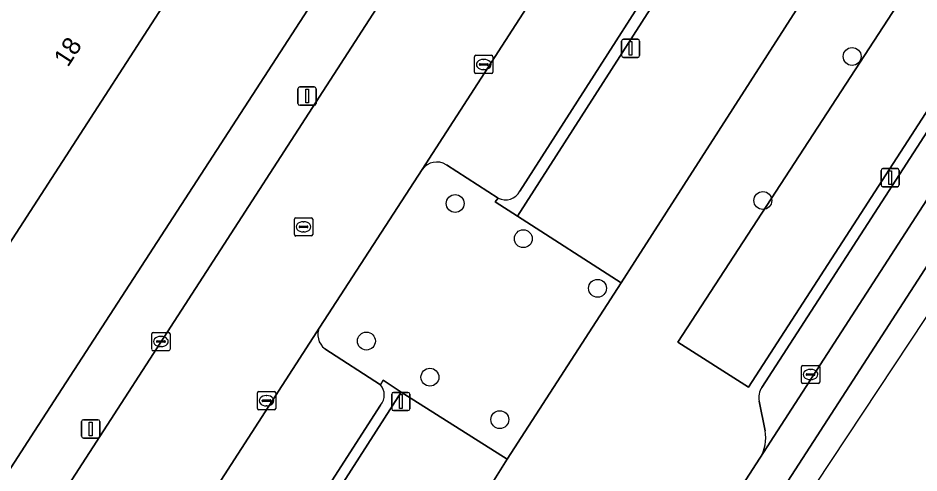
# Model space of a CAD drawing. Extents: x 161139 to 161601, y 381708 to 382245.
# Drawn here: x 161469.39 to 161518.67, y 381997.72 to 382022.6 of the extents above; entities that cross this region are included whole.
import ezdxf

# ---------------------------------------------------------------- set-up
doc = ezdxf.new("R2010")
doc.units = 0
for name, color, linetype in [('IMGEO_Boom', 7, 'Continuous'), ('IMGEO_Erf', 7, 'Continuous'), ('IMGEO_Groenvoorziening', 7, 'Continuous'), ('IMGEO_Kolk', 7, 'Continuous'), ('IMGEO_Lichtmast', 7, 'Continuous'), ('IMGEO_Pand', 7, 'Continuous'), ('IMGEO_Pand_nummerreeks', 7, 'Continuous'), ('IMGEO_Parkeervlak_open', 7, 'Continuous'), ('IMGEO_Rijbaan_lokaal_gesloten', 7, 'Continuous'), ('IMGEO_Rijbaan_lokaal_open', 7, 'Continuous'), ('IMGEO_Rioolput', 7, 'Continuous'), ('IMGEO_Voetpad_open', 7, 'Continuous')]:
    doc.layers.add(name, color=color, linetype=linetype)

msp = doc.modelspace()

# ---------------------------------------------------------------- linework, layer by layer
at = {"layer": 'IMGEO_Boom'}
for centre in [(161515.014, 382020.495), (161493.303, 382012.455), (161510.134, 382012.617), (161497.03, 382010.529), (161501.091, 382007.818), (161488.447, 382004.932), (161491.921, 382002.955), (161495.742, 382000.635)]:
    msp.add_circle(centre, 0.489, dxfattribs=at)
at = {"layer": 'IMGEO_Erf'}
msp.add_lwpolyline([(161320.525, 382089.631), (161313.623, 382083.997), (161443.483, 382000), (161462.38, 381987.777), (161470.3, 382000), (161498.24, 382043.117), (161359.011, 382133.266)], dxfattribs=at)
msp.add_lwpolyline([(161465.14, 382043.824), (161467.861, 382048.029), (161476.169, 382042.655), (161476.375, 382042.973), (161486.031, 382036.726), (161463.237, 382001.496), (161453.51, 382007.789), (161458.187, 382015.018), (161459.285, 382014.308), (161462.86, 382019.835), (161460.857, 382021.131), (161461.57, 382022.233), (161460.898, 382022.668), (161459.22, 382020.074), (161456.379, 382021.912), (161458.057, 382024.506), (161451.086, 382029.016), (161453.802, 382033.215), (161455.991, 382036.598), (161466.421, 382029.851), (161466.963, 382030.689), (161462.496, 382033.579), (161463.339, 382034.883), (161460.531, 382036.7)], close=True, dxfattribs=at)
at = {"layer": 'IMGEO_Groenvoorziening'}
for points in [[(161508.122, 382030.748), (161508.66, 382030.403), (161496.714, 382011.755), (161502.377, 382008.114), (161503.136, 382009.288), (161516.685, 382030.422)], [(161521.27, 382028.087), (161520.791, 382028.402), (161505.482, 382004.864), (161509.353, 382002.408), (161522.399, 382022.591)], [(161495.145, 381996.879), (161496.146, 381998.479), (161490.355, 382002.133), (161478.633, 381983.86), (161478.108, 381984.171)]]:
    msp.add_lwpolyline(points, dxfattribs=at)
at = {"layer": 'IMGEO_Kolk'}
for p, q in [((161494.363, 382019.63), (161494.363, 382020.482)), ((161494.438, 382020.556), (161495.29, 382020.556)), ((161494.851, 382020.336), (161494.876, 382020.336)), ((161495.364, 382020.482), (161495.364, 382019.63)), ((161494.622, 382020.05), (161494.622, 382020.062)), ((161495.06, 382020.013), (161494.662, 382020.013)), ((161494.665, 382020.099), (161495.063, 382020.099)), ((161494.874, 382019.776), (161494.849, 382019.776)), ((161495.106, 382020.062), (161495.106, 382020.05)), ((161495.29, 382019.556), (161494.438, 382019.556)), ((161476.707, 382004.48), (161476.707, 382005.332)), ((161476.782, 382005.406), (161477.634, 382005.406)), ((161477.195, 382005.186), (161477.22, 382005.186)), ((161477.708, 382005.332), (161477.708, 382004.48)), ((161476.966, 382004.9), (161476.966, 382004.912)), ((161477.404, 382004.863), (161477.006, 382004.863)), ((161477.009, 382004.949), (161477.407, 382004.949)), ((161477.218, 382004.626), (161477.193, 382004.626)), ((161477.45, 382004.912), (161477.45, 382004.9)), ((161477.634, 382004.406), (161476.782, 382004.406)), ((161512.241, 382002.678), (161512.241, 382003.53)), ((161512.316, 382003.604), (161513.168, 382003.604)), ((161513.242, 382003.53), (161513.242, 382002.678)), ((161512.5, 382003.098), (161512.5, 382003.11)), ((161512.938, 382003.061), (161512.54, 382003.061)), ((161512.543, 382003.147), (161512.941, 382003.147)), ((161512.729, 382003.384), (161512.754, 382003.384)), ((161512.984, 382003.11), (161512.984, 382003.098)), ((161513.168, 382002.604), (161512.316, 382002.604)), ((161512.752, 382002.824), (161512.727, 382002.824)), ((161482.484, 382001.243), (161482.484, 382002.095)), ((161482.559, 382002.169), (161483.411, 382002.169)), ((161483.485, 382002.095), (161483.485, 382001.243)), ((161482.743, 382001.663), (161482.743, 382001.675)), ((161483.181, 382001.626), (161482.783, 382001.626)), ((161482.786, 382001.712), (161483.184, 382001.712)), ((161482.972, 382001.949), (161482.997, 382001.949)), ((161483.227, 382001.675), (161483.227, 382001.663)), ((161483.411, 382001.169), (161482.559, 382001.169)), ((161482.995, 382001.389), (161482.97, 382001.389))]:
    msp.add_line(p, q, dxfattribs=at)
for points in [[(161494.363, 382019.63), (161494.363, 382020.482)], [(161494.438, 382020.556), (161495.29, 382020.556)], [(161495.364, 382020.482), (161495.364, 382019.63)], [(161495.29, 382019.556), (161494.438, 382019.556)], [(161476.707, 382004.48), (161476.707, 382005.332)], [(161476.782, 382005.406), (161477.634, 382005.406)], [(161477.708, 382005.332), (161477.708, 382004.48)], [(161477.634, 382004.406), (161476.782, 382004.406)], [(161512.241, 382002.678), (161512.241, 382003.53)], [(161512.316, 382003.604), (161513.168, 382003.604)], [(161513.242, 382003.53), (161513.242, 382002.678)], [(161513.168, 382002.604), (161512.316, 382002.604)], [(161482.484, 382001.243), (161482.484, 382002.095)], [(161482.559, 382002.169), (161483.411, 382002.169)], [(161483.485, 382002.095), (161483.485, 382001.243)], [(161483.411, 382001.169), (161482.559, 382001.169)]]:
    msp.add_lwpolyline(points, dxfattribs=at)
for centre, radius, start, end in [((161494.44, 382020.48), 0.0765, 91.552, 178.448), ((161494.44, 382020.48), 0.0765, 91.552, 178.448), ((161495.288, 382020.48), 0.0765, 1.552, 88.448), ((161495.288, 382020.48), 0.0765, 1.552, 88.448), ((161494.662, 382020.059), 0.0403, 85.8775, 175.7526), ((161494.659, 382020.049), 0.0366, 178.938, 274.7102), ((161495.063, 382020.056), 0.043, 264.8664, 352.4533), ((161495.067, 382020.061), 0.0386, 1.7309, 96.639), ((161494.44, 382019.632), 0.0765, 181.552, 268.448), ((161494.44, 382019.632), 0.0765, 181.552, 268.448), ((161495.288, 382019.632), 0.0765, 271.552, 358.448), ((161495.288, 382019.632), 0.0765, 271.552, 358.448), ((161476.784, 382005.33), 0.0765, 91.552, 178.448), ((161476.784, 382005.33), 0.0765, 91.552, 178.448), ((161477.632, 382005.33), 0.0765, 1.552, 88.448), ((161477.632, 382005.33), 0.0765, 1.552, 88.448), ((161477.006, 382004.909), 0.0403, 85.8775, 175.7526), ((161477.003, 382004.899), 0.0366, 178.938, 274.7102), ((161477.407, 382004.906), 0.043, 264.8664, 352.4533), ((161477.411, 382004.911), 0.0386, 1.7309, 96.639), ((161476.784, 382004.482), 0.0765, 181.552, 268.448), ((161476.784, 382004.482), 0.0765, 181.552, 268.448), ((161477.632, 382004.482), 0.0765, 271.552, 358.448), ((161477.632, 382004.482), 0.0765, 271.552, 358.448), ((161512.318, 382003.528), 0.0765, 91.552, 178.448), ((161512.318, 382003.528), 0.0765, 91.552, 178.448), ((161513.166, 382003.528), 0.0765, 1.552, 88.448), ((161513.166, 382003.528), 0.0765, 1.552, 88.448), ((161512.54, 382003.107), 0.0403, 85.8775, 175.7526), ((161512.537, 382003.097), 0.0366, 178.938, 274.7102), ((161512.941, 382003.104), 0.043, 264.8664, 352.4533), ((161512.945, 382003.109), 0.0386, 1.7309, 96.639), ((161512.318, 382002.68), 0.0765, 181.552, 268.448), ((161512.318, 382002.68), 0.0765, 181.552, 268.448), ((161513.166, 382002.68), 0.0765, 271.552, 358.448), ((161513.166, 382002.68), 0.0765, 271.552, 358.448), ((161482.561, 382002.093), 0.0765, 91.552, 178.448), ((161482.561, 382002.093), 0.0765, 91.552, 178.448), ((161483.409, 382002.093), 0.0765, 1.552, 88.448), ((161483.409, 382002.093), 0.0765, 1.552, 88.448), ((161482.783, 382001.672), 0.0403, 85.8775, 175.7526), ((161482.78, 382001.662), 0.0366, 178.938, 274.7102), ((161483.184, 382001.669), 0.043, 264.8664, 352.4533), ((161483.188, 382001.674), 0.0386, 1.7309, 96.639), ((161482.561, 382001.245), 0.0765, 181.552, 268.448), ((161482.561, 382001.245), 0.0765, 181.552, 268.448), ((161483.409, 382001.245), 0.0765, 271.552, 358.448), ((161483.409, 382001.245), 0.0765, 271.552, 358.448)]:
    msp.add_arc(centre, radius, start, end, dxfattribs=at)
for centre, major_axis, ratio, start_param, end_param in [((161494.85, 382020.056), (-0.387, 0.002), 0.722429, 4.712389, 7.853982), ((161494.875, 382020.056), (-0.39, 0.002), 0.717154, 1.570796, 4.712389), ((161477.194, 382004.906), (-0.387, 0.002), 0.722429, 4.712389, 7.853982), ((161477.219, 382004.906), (-0.39, 0.002), 0.717154, 1.570796, 4.712389), ((161512.728, 382003.104), (-0.387, 0.002), 0.722429, 4.712389, 7.853982), ((161512.753, 382003.104), (-0.39, 0.002), 0.717154, 1.570796, 4.712389), ((161482.971, 382001.669), (-0.387, 0.002), 0.722429, 4.712389, 7.853982), ((161482.996, 382001.669), (-0.39, 0.002), 0.717154, 1.570796, 4.712389)]:
    msp.add_ellipse(centre, major_axis=major_axis, ratio=ratio, start_param=start_param, end_param=end_param, dxfattribs=at)
at = {"layer": 'IMGEO_Lichtmast'}
for p, q in [((161502.403, 382020.538), (161502.403, 382021.338)), ((161502.403, 382021.338), (161502.403, 382020.538)), ((161502.503, 382021.438), (161503.293, 382021.438)), ((161503.293, 382021.438), (161502.503, 382021.438)), ((161503.393, 382021.338), (161503.393, 382020.538)), ((161503.393, 382020.538), (161503.393, 382021.338)), ((161503.293, 382020.438), (161502.503, 382020.438)), ((161502.503, 382020.438), (161503.293, 382020.438)), ((161484.805, 382018.828), (161485.595, 382018.828)), ((161485.595, 382018.828), (161484.805, 382018.828)), ((161484.705, 382017.928), (161484.705, 382018.728)), ((161484.705, 382018.728), (161484.705, 382017.928)), ((161485.695, 382018.728), (161485.695, 382017.928)), ((161485.695, 382017.928), (161485.695, 382018.728)), ((161485.595, 382017.828), (161484.805, 382017.828)), ((161484.805, 382017.828), (161485.595, 382017.828)), ((161516.699, 382014.366), (161517.489, 382014.366)), ((161517.489, 382014.366), (161516.699, 382014.366)), ((161516.599, 382013.466), (161516.599, 382014.266)), ((161516.599, 382014.266), (161516.599, 382013.466)), ((161517.589, 382014.266), (161517.589, 382013.466)), ((161517.589, 382013.466), (161517.589, 382014.266)), ((161517.489, 382013.366), (161516.699, 382013.366)), ((161516.699, 382013.366), (161517.489, 382013.366)), ((161489.831, 382001.227), (161489.831, 382002.027)), ((161489.831, 382002.027), (161489.831, 382001.227)), ((161489.931, 382002.127), (161490.721, 382002.127)), ((161490.721, 382002.127), (161489.931, 382002.127)), ((161490.821, 382002.027), (161490.821, 382001.227)), ((161490.821, 382001.227), (161490.821, 382002.027)), ((161490.721, 382001.127), (161489.931, 382001.127)), ((161489.931, 382001.127), (161490.721, 382001.127)), ((161472.971, 382000.629), (161473.761, 382000.629)), ((161473.761, 382000.629), (161472.971, 382000.629)), ((161472.871, 381999.729), (161472.871, 382000.529)), ((161472.871, 382000.529), (161472.871, 381999.729)), ((161473.861, 382000.529), (161473.861, 381999.729)), ((161473.861, 381999.729), (161473.861, 382000.529)), ((161473.761, 381999.629), (161472.971, 381999.629)), ((161472.971, 381999.629), (161473.761, 381999.629))]:
    msp.add_line(p, q, dxfattribs=at)
for points in [[(161502.823, 382021.313), (161502.973, 382021.313), (161502.973, 382020.563), (161502.823, 382020.563), (161502.823, 382021.313)], [(161485.125, 382018.703), (161485.275, 382018.703), (161485.275, 382017.953), (161485.125, 382017.953), (161485.125, 382018.703)], [(161517.019, 382014.241), (161517.169, 382014.241), (161517.169, 382013.491), (161517.019, 382013.491), (161517.019, 382014.241)], [(161490.251, 382002.002), (161490.401, 382002.002), (161490.401, 382001.252), (161490.251, 382001.252), (161490.251, 382002.002)], [(161473.291, 382000.504), (161473.441, 382000.504), (161473.441, 381999.754), (161473.291, 381999.754), (161473.291, 382000.504)]]:
    msp.add_lwpolyline(points, dxfattribs=at)
for centre, start, end in [((161502.503, 382021.338), 90, 180), ((161502.503, 382021.338), 90, 180), ((161503.293, 382021.338), 0, 90), ((161503.293, 382021.338), 360, 90), ((161502.503, 382020.538), 180, 270), ((161502.503, 382020.538), 180, 270), ((161503.293, 382020.538), 270, 0), ((161503.293, 382020.538), 270, 0), ((161484.805, 382018.728), 90, 180), ((161484.805, 382018.728), 90, 180), ((161485.595, 382018.728), 0, 90), ((161485.595, 382018.728), 360, 90), ((161484.805, 382017.928), 180, 270), ((161484.805, 382017.928), 180, 270), ((161485.595, 382017.928), 270, 0), ((161485.595, 382017.928), 270, 0), ((161516.699, 382014.266), 90, 180), ((161516.699, 382014.266), 90, 180), ((161517.489, 382014.266), 0, 90), ((161517.489, 382014.266), 360, 90), ((161516.699, 382013.466), 180, 270), ((161516.699, 382013.466), 180, 270), ((161517.489, 382013.466), 270, 0), ((161517.489, 382013.466), 270, 0), ((161489.931, 382002.027), 90, 180), ((161489.931, 382002.027), 90, 180), ((161490.721, 382002.027), 0, 90), ((161490.721, 382002.027), 360, 90), ((161489.931, 382001.227), 180, 270), ((161489.931, 382001.227), 180, 270), ((161490.721, 382001.227), 270, 0), ((161490.721, 382001.227), 270, 0), ((161472.971, 382000.529), 90, 180), ((161472.971, 382000.529), 90, 180), ((161473.761, 382000.529), 0, 90), ((161473.761, 382000.529), 360, 90), ((161472.971, 381999.729), 180, 270), ((161472.971, 381999.729), 180, 270), ((161473.761, 381999.729), 270, 0), ((161473.761, 381999.729), 270, 0)]:
    msp.add_arc(centre, 0.1, start, end, dxfattribs=at)
at = {"layer": 'IMGEO_Pand'}
msp.add_lwpolyline([(161486.031, 382036.726), (161476.375, 382042.973), (161476.169, 382042.655), (161467.861, 382048.029), (161465.14, 382043.824), (161460.531, 382036.7), (161463.339, 382034.883), (161462.496, 382033.579), (161466.963, 382030.689), (161466.421, 382029.851), (161455.991, 382036.598), (161453.802, 382033.215), (161451.086, 382029.016), (161458.057, 382024.506), (161456.379, 382021.912), (161459.22, 382020.074), (161460.898, 382022.668), (161461.57, 382022.233), (161460.857, 382021.131), (161462.86, 382019.835), (161459.285, 382014.308), (161458.187, 382015.018), (161453.51, 382007.789), (161463.237, 382001.496)], close=True, dxfattribs=at)
at = {"layer": 'IMGEO_Parkeervlak_open'}
for points in [[(161504.966, 382035.175), (161491.489, 382014.315)], [(161496.841, 382013.134), (161508.122, 382030.748)], [(161509.971, 381998.522), (161525.295, 382022.249)], [(161522.031, 382020.897), (161510.074, 382002.396)], [(161492.819, 382014.575), (161495.645, 382012.744)], [(161485.898, 382005.698), (161472.847, 381985.485), (161473.39, 381985.794)], [(161489.222, 382002.546), (161486.182, 382004.514)], [(161509.927, 382001.645), (161510.252, 382000.03)], [(161478.108, 381984.171), (161489.225, 382001.433)]]:
    msp.add_lwpolyline(points, dxfattribs=at)
for centre, radius, start, end in [((161492.296, 382013.717), 1.005, 58.664, 143.4584), ((161496.039, 382013.564), 0.91, 244.3382, 331.7827), ((161486.719, 382005.269), 0.926, 152.3859, 234.5909), ((161488.547, 382001.988), 0.876, 320.7099, 39.599), ((161510.848, 382001.855), 0.944, 145.0204, 192.8296), ((161508.23, 381999.627), 2.062, 327.6032, 11.2859)]:
    msp.add_arc(centre, radius, start, end, dxfattribs=at)
at = {"layer": 'IMGEO_Rijbaan_lokaal_gesloten'}
msp.add_lwpolyline([(161494.211, 381970.546), (161527.059, 382021.311), (161525.43, 382022.403), (161525.295, 382022.249), (161509.971, 381998.522), (161507.874, 381995.285), (161492.716, 381971.881), (161492.536, 381971.604)], close=True, dxfattribs=at)
at = {"layer": 'IMGEO_Rijbaan_lokaal_open'}
for points in [[(161500.799, 382041.385), (161464.955, 381985.959)], [(161485.898, 382005.698), (161491.489, 382014.315), (161504.966, 382035.175), (161506.503, 382037.599), (161506.547, 382037.659), (161506.592, 382037.718)], [(161470.158, 381981.373), (161471.001, 381982.663), (161472.847, 381985.485), (161485.898, 382005.698)]]:
    msp.add_lwpolyline(points, dxfattribs=at)
msp.add_lwpolyline([(161495.077, 381969.984), (161528.454, 382020.403), (161527.059, 382021.311), (161494.211, 381970.546)], close=True, dxfattribs=at)
at = {"layer": 'IMGEO_Rioolput'}
for p, q in [((161484.508, 382010.751), (161484.508, 382011.603)), ((161484.583, 382011.677), (161485.435, 382011.677)), ((161484.996, 382011.457), (161485.021, 382011.457)), ((161485.509, 382011.603), (161485.509, 382010.751)), ((161484.767, 382011.171), (161484.767, 382011.183)), ((161485.205, 382011.134), (161484.807, 382011.134)), ((161484.81, 382011.22), (161485.208, 382011.22)), ((161485.019, 382010.897), (161484.994, 382010.897)), ((161485.251, 382011.183), (161485.251, 382011.171)), ((161485.435, 382010.677), (161484.583, 382010.677))]:
    msp.add_line(p, q, dxfattribs=at)
for points in [[(161484.508, 382010.751), (161484.508, 382011.603)], [(161484.583, 382011.677), (161485.435, 382011.677)], [(161485.509, 382011.603), (161485.509, 382010.751)], [(161485.435, 382010.677), (161484.583, 382010.677)]]:
    msp.add_lwpolyline(points, dxfattribs=at)
for centre, radius, start, end in [((161484.585, 382011.601), 0.0765, 91.552, 178.448), ((161484.585, 382011.601), 0.0765, 91.552, 178.448), ((161485.433, 382011.601), 0.0765, 1.552, 88.448), ((161485.433, 382011.601), 0.0765, 1.552, 88.448), ((161484.807, 382011.18), 0.0403, 85.8775, 175.7526), ((161484.804, 382011.17), 0.0366, 178.938, 274.7102), ((161485.208, 382011.177), 0.043, 264.8664, 352.4533), ((161485.212, 382011.182), 0.0386, 1.7309, 96.639), ((161484.585, 382010.753), 0.0765, 181.552, 268.448), ((161484.585, 382010.753), 0.0765, 181.552, 268.448), ((161485.433, 382010.753), 0.0765, 271.552, 358.448), ((161485.433, 382010.753), 0.0765, 271.552, 358.448)]:
    msp.add_arc(centre, radius, start, end, dxfattribs=at)
for centre, major_axis, ratio, start_param, end_param in [((161484.995, 382011.177), (-0.387, 0.002), 0.722429, 4.712389, 7.853982), ((161485.02, 382011.177), (-0.39, 0.002), 0.717154, 1.570796, 4.712389)]:
    msp.add_ellipse(centre, major_axis=major_axis, ratio=ratio, start_param=start_param, end_param=end_param, dxfattribs=at)
at = {"layer": 'IMGEO_Voetpad_open'}
msp.add_lwpolyline([(161500.799, 382041.385), (161498.24, 382043.117), (161470.3, 382000), (161462.38, 381987.777), (161464.955, 381985.959)], close=True, dxfattribs=at)
for points in [[(161526.187, 382027.747), (161522.604, 382022.847), (161522.399, 382022.591), (161509.353, 382002.408), (161505.482, 382004.864), (161520.791, 382028.402), (161516.669, 382031.191)], [(161495.645, 382012.744), (161495.494, 382012.545), (161496.714, 382011.755), (161508.66, 382030.403), (161508.122, 382030.748), (161496.841, 382013.134)], [(161516.685, 382030.422), (161503.136, 382009.288), (161502.377, 382008.114), (161496.146, 381998.479), (161495.145, 381996.879), (161481.528, 381976.053)], [(161510.074, 382002.396), (161522.031, 382020.897)], [(161486.182, 382004.514), (161489.222, 382002.546), (161489.364, 382002.789), (161490.355, 382002.133), (161496.146, 381998.479), (161502.377, 382008.114), (161496.714, 382011.755), (161495.494, 382012.545), (161495.645, 382012.744), (161492.819, 382014.575)], [(161491.489, 382014.315), (161485.898, 382005.698)], [(161489.225, 382001.433), (161478.108, 381984.171), (161478.633, 381983.86), (161490.355, 382002.133), (161489.364, 382002.789), (161489.222, 382002.546)], [(161510.252, 382000.03), (161509.927, 382001.645)], [(161507.874, 381995.285), (161509.971, 381998.522)]]:
    msp.add_lwpolyline(points, dxfattribs=at)
for centre, radius, start, end in [((161492.296, 382013.717), 1.005, 58.664, 143.4584), ((161496.039, 382013.564), 0.91, 244.3382, 331.7827), ((161486.719, 382005.269), 0.926, 152.3859, 234.5909), ((161488.547, 382001.988), 0.876, 320.7099, 39.599), ((161510.848, 382001.855), 0.944, 145.0204, 192.8296), ((161508.23, 381999.627), 2.062, 327.6032, 11.2859)]:
    msp.add_arc(centre, radius, start, end, dxfattribs=at)

# ---------------------------------------------------------------- texts
at = {"layer": 'IMGEO_Pand_nummerreeks'}
msp.add_text('18', height=1, rotation=57.0952, dxfattribs=at).set_placement((161472.12, 382019.865))

doc.saveas('drawing.dxf')
